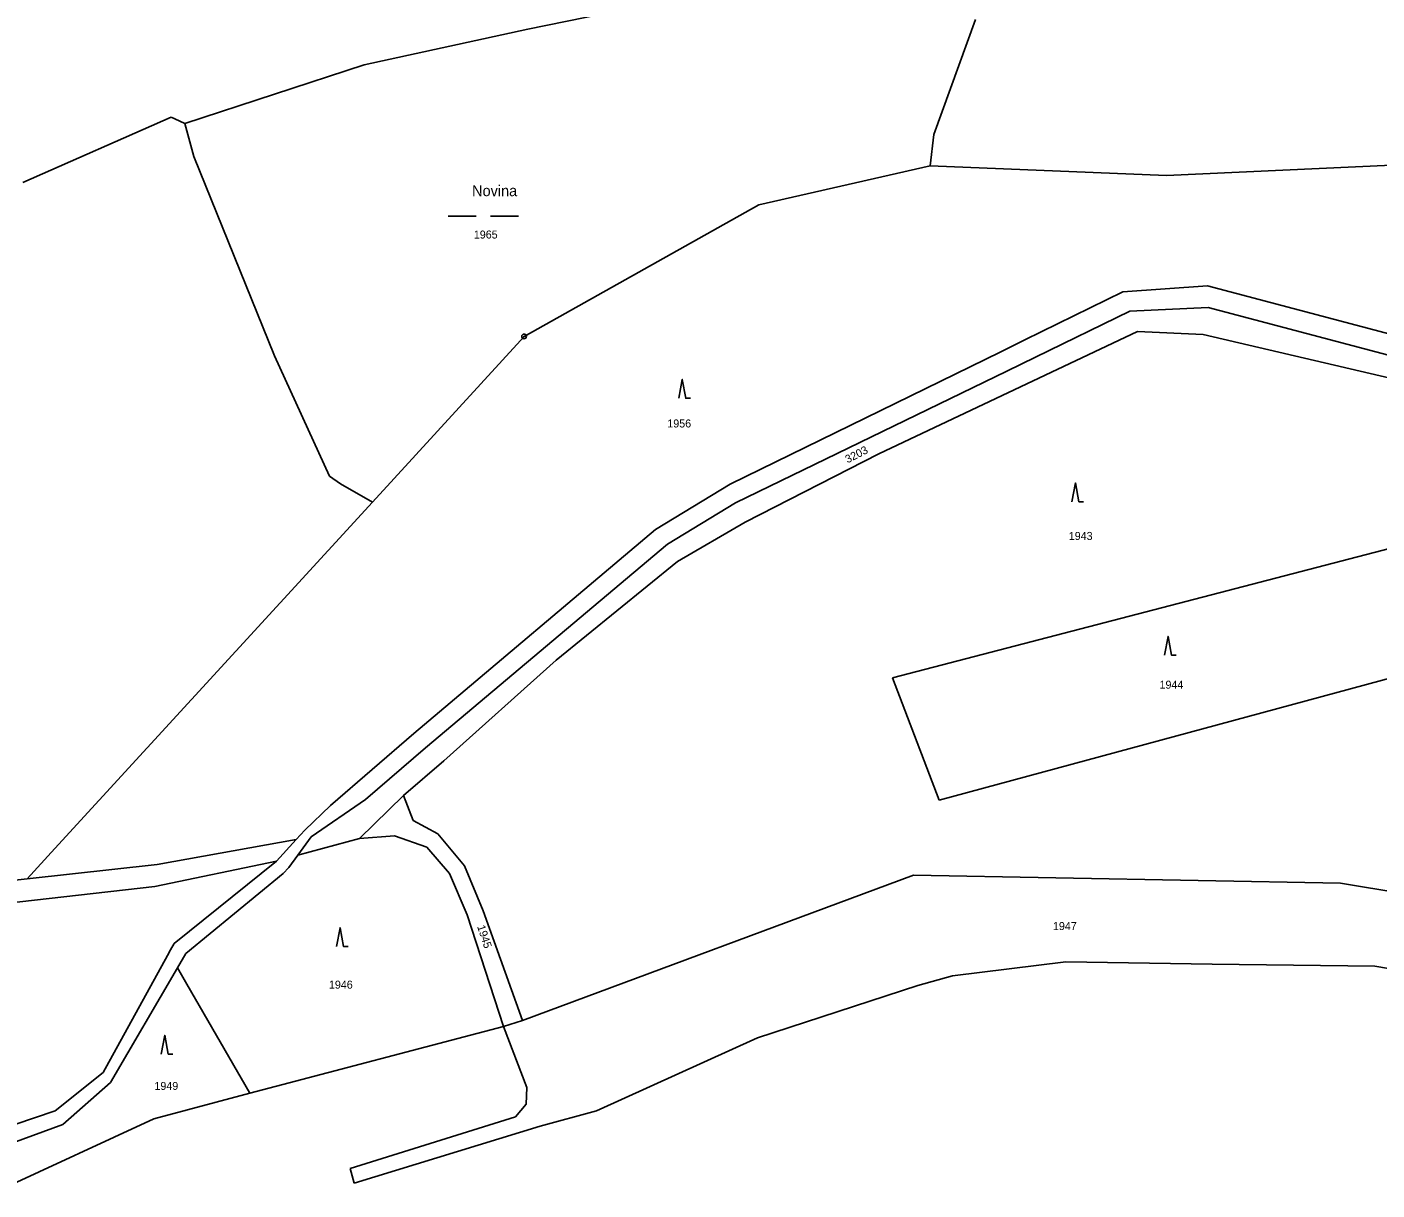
# Model space of a CAD drawing. Extents: x -736345 to -729997, y -1130177 to -1122501.
# Drawn here: x -731960.4 to -731673.6, y -1128667.9 to -1128420.7 of the extents above; entities that cross this region are included whole.
import ezdxf

# ---------------------------------------------------------------- set-up
doc = ezdxf.new("R2010")
doc.units = 0
for name, color, linetype in [('Vrstva 1', 7, 'Continuous'), ('Vrstva 15', 7, 'Continuous'), ('Vrstva 18', 7, 'Continuous'), ('Vrstva 25', 7, 'Continuous')]:
    doc.layers.add(name, color=color, linetype=linetype)

msp = doc.modelspace()

# ---------------------------------------------------------------- linework, layer by layer
at = {"layer": 'Vrstva 1'}
for points in [[(-731837.64, -1128417.85), (-731853.98, -1128421.17)], [(-731758.9, -1128419.12), (-731767.77, -1128443.56)], [(-731853.98, -1128421.17), (-731888.73, -1128428.78)], [(-731888.73, -1128428.78), (-731926.86, -1128441.23)], [(-731929.78, -1128439.87), (-731961.23, -1128453.77)], [(-731928.98, -1128440.25), (-731929.78, -1128439.87)], [(-731926.86, -1128441.23), (-731928.98, -1128440.25)], [(-731926.86, -1128441.23), (-731924.93, -1128448.24)], [(-731767.77, -1128443.56), (-731768.55, -1128450.22)], [(-731924.93, -1128448.24), (-731907.8, -1128490.63)], [(-731718.33, -1128452.3), (-731653.49, -1128449.29)], [(-731804.89, -1128458.55), (-731768.55, -1128450.22)], [(-731768.55, -1128450.22), (-731718.33, -1128452.3)], [(-731854.79, -1128486.49), (-731804.89, -1128458.55)], [(-731727.59, -1128477.04), (-731748.39, -1128487.21)], [(-731709.64, -1128475.71), (-731727.59, -1128477.04)], [(-731604.98, -1128503.42), (-731709.64, -1128475.71)], [(-731726.09, -1128481.14), (-731709.47, -1128480.36)], [(-731709.47, -1128480.36), (-731606.12, -1128507.66)], [(-731746.14, -1128490.89), (-731726.09, -1128481.14)], [(-731854.79, -1128486.49), (-731886.97, -1128521.68)], [(-731724.52, -1128485.43), (-731779.41, -1128511.46)], [(-731710.51, -1128486.05), (-731724.52, -1128485.43)], [(-731641.7, -1128502.14), (-731710.51, -1128486.05)], [(-731748.39, -1128487.21), (-731753.55, -1128489.74)], [(-731907.8, -1128490.63), (-731896.1, -1128516.17)], [(-731753.55, -1128489.74), (-731811.04, -1128517.86)], [(-731752.23, -1128493.85), (-731746.14, -1128490.89)], [(-731809.87, -1128521.88), (-731752.23, -1128493.85)], [(-731779.41, -1128511.46), (-731807.82, -1128525.95)], [(-731896.1, -1128516.17), (-731893.81, -1128517.79)], [(-731893.81, -1128517.79), (-731886.97, -1128521.68)], [(-731811.04, -1128517.86), (-731826.84, -1128527.49)], [(-731954.44, -1128595.31), (-731886.97, -1128521.68)], [(-731824.35, -1128530.66), (-731809.87, -1128521.88)], [(-731807.82, -1128525.95), (-731822.2, -1128534.32)], [(-731826.84, -1128527.49), (-731878.22, -1128570.9)], [(-731875.74, -1128573.92), (-731824.35, -1128530.66)], [(-731776.51, -1128559.06), (-731669.04, -1128531.06)], [(-731822.2, -1128534.32), (-731848, -1128555.32)], [(-731848, -1128555.32), (-731871.85, -1128576.67)], [(-731660.41, -1128556.31), (-731766.61, -1128585.06)], [(-731766.61, -1128585.06), (-731776.51, -1128559.06)], [(-731878.22, -1128570.9), (-731895.92, -1128586.19)], [(-731875.74, -1128573.92), (-731888.45, -1128584.87)], [(-731871.85, -1128576.67), (-731880.41, -1128584.03)], [(-731880.41, -1128584.03), (-731889.76, -1128593.16)], [(-731880.41, -1128584.03), (-731878.32, -1128589.38)], [(-731895.92, -1128586.19), (-731901.38, -1128591.44)], [(-731888.45, -1128584.87), (-731900.03, -1128592.86)], [(-731878.32, -1128589.38), (-731873.08, -1128592.19)], [(-731901.38, -1128591.44), (-731903.21, -1128593.43)], [(-731889.76, -1128593.16), (-731882.29, -1128592.62)], [(-731882.29, -1128592.62), (-731875.43, -1128595)], [(-731873.08, -1128592.19), (-731867.46, -1128599.01)], [(-731960.36, -1128601.77), (-731954.44, -1128595.31)], [(-731903.21, -1128593.43), (-731932.71, -1128598.7)], [(-731903.21, -1128593.43), (-731907.4, -1128597.97)], [(-731900.03, -1128592.86), (-731902.88, -1128596.73)], [(-731902.88, -1128596.73), (-731889.76, -1128593.16)], [(-731875.43, -1128595), (-731870.63, -1128600.62)], [(-731907.4, -1128597.97), (-731933.2, -1128603.41)], [(-731907.4, -1128597.97), (-731929.12, -1128615.49)], [(-731904.79, -1128599.33), (-731902.88, -1128596.73)], [(-731932.71, -1128598.7), (-731960.36, -1128601.77)], [(-731926.65, -1128617.62), (-731905.93, -1128600.62)], [(-731905.93, -1128600.62), (-731904.79, -1128599.33)], [(-731870.63, -1128600.62), (-731866.88, -1128609.42)], [(-731867.46, -1128599.01), (-731863.5, -1128608.58)], [(-731772.08, -1128600.99), (-731855.12, -1128631.89)], [(-731681.34, -1128602.65), (-731772.08, -1128600.99)], [(-731960.36, -1128601.77), (-731994.6, -1128605.55)], [(-731933.2, -1128603.41), (-731994.4, -1128610.33)], [(-731641.68, -1128609.25), (-731681.34, -1128602.65)], [(-731866.88, -1128609.42), (-731859.14, -1128633.14)], [(-731863.5, -1128608.58), (-731855.12, -1128631.89)], [(-731929.12, -1128615.49), (-731929.86, -1128616.85)], [(-731930.54, -1128618.07), (-731944.17, -1128642.94)], [(-731929.86, -1128616.85), (-731930.54, -1128618.07)], [(-731928.43, -1128620.65), (-731926.65, -1128617.62)], [(-731942.67, -1128645.04), (-731928.43, -1128620.65)], [(-731926.41, -1128624.15), (-731928.43, -1128620.65)], [(-731739.73, -1128619.36), (-731763.76, -1128622.36)], [(-731708.66, -1128619.86), (-731739.73, -1128619.36)], [(-731674.04, -1128620.3), (-731708.66, -1128619.86)], [(-731619.34, -1128629.63), (-731674.04, -1128620.3)], [(-731913.01, -1128647.31), (-731926.41, -1128624.15)], [(-731763.76, -1128622.36), (-731771.14, -1128624.45)], [(-731771.14, -1128624.45), (-731805.23, -1128635.57)], [(-731855.12, -1128631.89), (-731859.14, -1128633.14)], [(-731859.14, -1128633.14), (-731913.01, -1128647.31)], [(-731854.19, -1128646.11), (-731859.14, -1128633.14)], [(-731805.23, -1128635.57), (-731839.4, -1128651.03)], [(-731954.38, -1128651.06), (-731944.17, -1128642.94)], [(-731952.73, -1128653.94), (-731942.67, -1128645.04)], [(-731854.36, -1128649.67), (-731854.19, -1128646.11)], [(-731913.01, -1128647.31), (-731933.4, -1128652.74)], [(-731856.63, -1128652.34), (-731854.36, -1128649.67)], [(-731971.6, -1128656.84), (-731954.38, -1128651.06)], [(-731933.4, -1128652.74), (-731966.29, -1128667.88)], [(-731891.7, -1128663.28), (-731856.63, -1128652.34)], [(-731839.4, -1128651.03), (-731851.39, -1128654.29)], [(-731969.84, -1128660.22), (-731952.73, -1128653.94)], [(-731851.39, -1128654.29), (-731890.89, -1128666.46)], [(-731890.89, -1128666.46), (-731891.7, -1128663.28)]]:
    msp.add_lwpolyline(points, dxfattribs=at)
at = {"layer": 'Vrstva 25'}
for points in [[(-731870.94, -1128460.91), (-731864.94, -1128460.91)], [(-731861.94, -1128460.91), (-731855.94, -1128460.91)], [(-731821.95, -1128499.63), (-731821.2, -1128495.63), (-731820.45, -1128499.63), (-731819.45, -1128499.63)], [(-731738.43, -1128521.62), (-731737.68, -1128517.62), (-731736.93, -1128521.62), (-731735.93, -1128521.62)], [(-731718.74, -1128554.25), (-731717.99, -1128550.25), (-731717.24, -1128554.25), (-731716.24, -1128554.25)], [(-731894.62, -1128616.15), (-731893.87, -1128612.15), (-731893.12, -1128616.15), (-731892.12, -1128616.15)], [(-731931.88, -1128639.01), (-731931.13, -1128635.01), (-731930.38, -1128639.01), (-731929.38, -1128639.01)]]:
    msp.add_lwpolyline(points, dxfattribs=at)
for radius in [0.5, 0.032]:
    msp.add_circle((-731854.79, -1128486.49), radius, dxfattribs=at)

# ---------------------------------------------------------------- texts
at = {"layer": 'Vrstva 15'}
msp.add_text('Novina', height=2.3, dxfattribs=at).set_placement((-731865.83, -1128456.69))
at = {"layer": 'Vrstva 18'}
for s, p in [('1965', (-731865.46, -1128465.69)), ('1956', (-731824.36, -1128505.84)), ('1943', (-731739.09, -1128529.74)), ('1944', (-731719.81, -1128561.35)), ('1947', (-731742.45, -1128612.64)), ('1946', (-731896.24, -1128625.09)), ('1949', (-731933.31, -1128646.62))]:
    msp.add_text(s, height=1.7, dxfattribs=at).set_placement(p)
for s, rotation, p in [('3203', 27.20022, (-731786.054, -1128513.481)), ('1945', 288.40229, (-731864.778, -1128611.896))]:
    msp.add_text(s, height=1.7, rotation=rotation, dxfattribs=at).set_placement(p)

doc.saveas('drawing.dxf')
